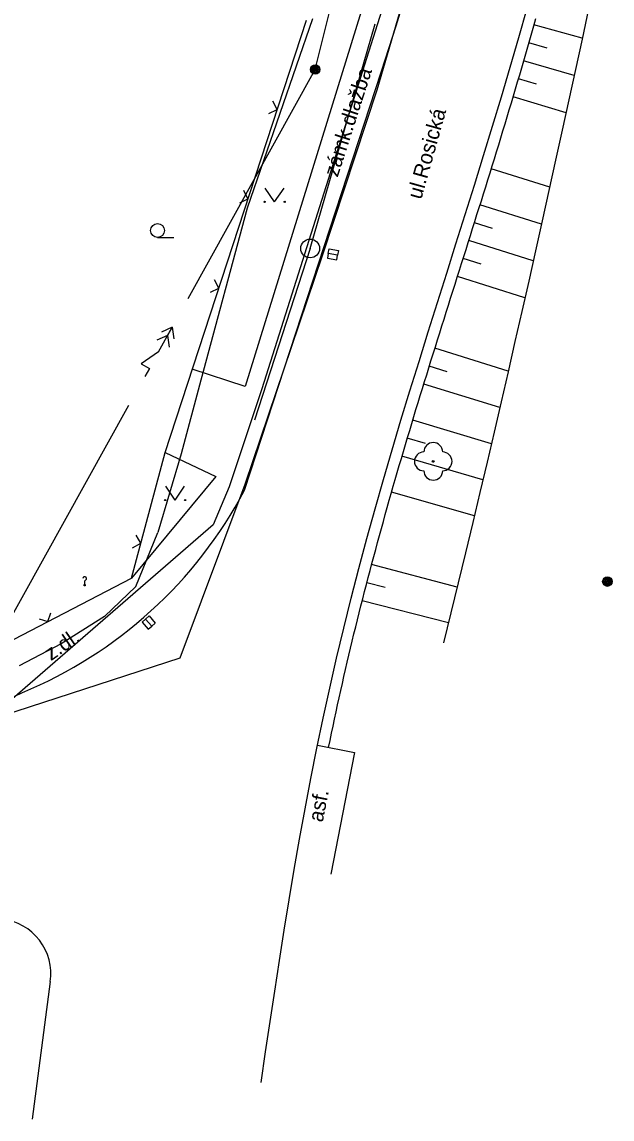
# Model space of a CAD drawing. Extents: x -614582 to -612559, y -1157748 to -1156203.
# Drawn here: x -613339.9 to -613308.5, y -1157413.8 to -1157355.5 of the extents above; entities that cross this region are included whole.
import ezdxf

# ---------------------------------------------------------------- set-up
doc = ezdxf.new("R2010")
doc.units = 0
for name, color, linetype in [('Vrstva 1', 7, 'Continuous'), ('Vrstva 10', 7, 'Continuous'), ('Vrstva 11', 7, 'Continuous'), ('Vrstva 12', 7, 'Continuous'), ('Vrstva 13', 7, 'Continuous'), ('Vrstva 15', 7, 'Continuous'), ('Vrstva 17', 7, 'Continuous'), ('Vrstva 20', 7, 'Continuous'), ('Vrstva 4', 7, 'Continuous'), ('Vrstva 47', 7, 'Continuous'), ('Vrstva 48', 7, 'Continuous'), ('Vrstva 5', 7, 'Continuous'), ('Vrstva 7', 7, 'Continuous'), ('Vrstva 8', 7, 'Continuous')]:
    doc.layers.add(name, color=color, linetype=linetype)

# ---------------------------------------------------------------- blocks, each defined once
blk = doc.blocks.new('SC3403')
at = {"layer": 'Vrstva 10'}
blk.add_lwpolyline([(2.5, 0), (2.5, 2.5), (-2.5, 2.5), (-2.5, 0), (2.5, 0), (2.5, -2.5), (-2.5, -2.5), (-2.5, 0)], dxfattribs=at)
blk = doc.blocks.new('SC3405')
at = {"layer": 'Vrstva 11'}
for radius in [2.5, 2, 1.5, 1, 0.5]:
    blk.add_circle((0, 0), radius, dxfattribs=at)
blk = doc.blocks.new('PLOTDR')
at = {"layer": 'Vrstva 1'}
blk.add_lwpolyline([(-3.5, 3.5), (0, 0), (3.5, 3.5)], dxfattribs=at)
blk = doc.blocks.new('SC3400')
at = {"layer": 'Vrstva 10'}
blk.add_circle((0, 0), 5, dxfattribs=at)
blk = doc.blocks.new('SC3413')
at = {"layer": 'Vrstva 15'}
for points in [[(0, -0.625), (-10, 4.375), (-10, -0.625), (-15, -0.625)], [(10, -0.625), (5, 3.125)], [(15, -0.625), (10, 3.125)], [(0, -0.625), (15, -0.625), (10, -4.375)], [(15, -0.625), (10, -0.625), (5, -4.375)]]:
    blk.add_lwpolyline(points, dxfattribs=at)

msp = doc.modelspace()

# ---------------------------------------------------------------- linework, layer by layer
at = {"layer": 'Vrstva 12'}
for p, q in [((-613310.048, -1157356.334), (-613312.614, -1157355.613)), ((-613311.92, -1157356.851), (-613312.887, -1157356.575)), ((-613310.477, -1157358.314), (-613313.163, -1157357.536)), ((-613312.479, -1157358.779), (-613313.443, -1157358.496)), ((-613310.908, -1157360.294), (-613313.726, -1157359.455)), ((-613311.777, -1157364.246), (-613314.891, -1157363.282)), ((-613312.214, -1157366.216), (-613315.486, -1157365.191)), ((-613314.827, -1157366.447), (-613315.786, -1157366.145)), ((-613312.654, -1157368.182), (-613316.086, -1157367.099)), ((-613315.429, -1157368.355), (-613316.387, -1157368.053)), ((-613313.095, -1157370.141), (-613316.688, -1157369.006)), ((-613313.983, -1157374.041), (-613317.888, -1157372.822)), ((-613317.226, -1157374.074), (-613318.186, -1157373.777)), ((-613314.431, -1157375.979), (-613318.481, -1157374.732)), ((-613314.88, -1157377.909), (-613319.064, -1157376.645)), ((-613318.388, -1157377.891), (-613319.352, -1157377.603)), ((-613315.331, -1157379.829), (-613319.636, -1157378.562)), ((-613315.785, -1157381.741), (-613320.193, -1157380.483)), ((-613316.701, -1157385.545), (-613321.256, -1157384.339)), ((-613320.536, -1157385.558), (-613321.509, -1157385.306)), ((-613317.161, -1157387.439), (-613321.757, -1157386.275))]:
    msp.add_line(p, q, dxfattribs=at)
at = {"layer": 'Vrstva 15'}
for p, q in [((-613324.251, -1157357.996), (-613321.446, -1157346.735)), ((-613331.009, -1157370.179), (-613324.251, -1157357.996)), ((-613340.921, -1157388.046), (-613334.162, -1157375.863))]:
    msp.add_line(p, q, dxfattribs=at)
at = {"layer": 'Vrstva 17'}
for p, q in [((-613320.951, -1157359.076), (-613315.481, -1157340.156)), ((-613323.851, -1157367.846), (-613320.951, -1157359.076)), ((-613327.971, -1157380.056), (-613323.851, -1157367.846)), ((-613331.441, -1157389.296), (-613327.971, -1157380.056)), ((-613340.871, -1157392.376), (-613331.441, -1157389.296))]:
    msp.add_line(p, q, dxfattribs=at)
at = {"layer": 'Vrstva 20'}
for p, q in [((-613317.468, -1157344.596), (-613327.098, -1157374.978)), ((-613317.468, -1157344.596), (-613327.098, -1157374.978)), ((-613327.098, -1157374.978), (-613328.822, -1157380.208)), ((-613327.098, -1157374.978), (-613328.822, -1157380.208)), ((-613328.822, -1157380.208), (-613329.675, -1157382.226)), ((-613328.822, -1157380.208), (-613329.675, -1157382.226)), ((-613329.675, -1157382.226), (-613343.57, -1157394.253)), ((-613329.675, -1157382.226), (-613343.57, -1157394.253))]:
    msp.add_line(p, q, dxfattribs=at)
at = {"layer": 'Vrstva 4'}
for p, q in [((-613318.981, -1157345.736), (-613327.971, -1157374.856)), ((-613328.011, -1157380.386), (-613320.731, -1157358.076)), ((-613327.971, -1157374.856), (-613330.789, -1157373.935)), ((-613332.241, -1157378.376), (-613329.531, -1157379.656)), ((-613329.531, -1157379.656), (-613334.031, -1157385.066)), ((-613324.131, -1157393.956), (-613322.169, -1157394.346)), ((-613322.169, -1157394.346), (-613323.414, -1157400.809)), ((-613338.351, -1157406.526), (-613339.303, -1157413.844))]:
    msp.add_line(p, q, dxfattribs=at)
for points in [[(-613309.711, -1157354.772), (-613310.058, -1157356.383), (-613310.407, -1157357.994), (-613310.758, -1157359.604), (-613311.11, -1157361.214), (-613311.463, -1157362.824), (-613311.819, -1157364.434), (-613312.176, -1157366.043), (-613312.535, -1157367.651), (-613312.896, -1157369.259), (-613313.259, -1157370.867), (-613313.625, -1157372.474), (-613313.992, -1157374.08), (-613314.363, -1157375.686), (-613314.736, -1157377.291), (-613315.111, -1157378.896), (-613315.49, -1157380.5), (-613315.871, -1157382.103), (-613316.256, -1157383.706), (-613316.643, -1157385.308), (-613317.032, -1157386.91), (-613317.423, -1157388.511)], [(-613313.426, -1157356.298), (-613312.983, -1157354.721)], [(-613317.047, -1157370.16), (-613316.93, -1157369.789), (-613316.814, -1157369.419), (-613316.697, -1157369.049), (-613316.58, -1157368.679), (-613316.463, -1157368.308), (-613316.346, -1157367.938), (-613316.229, -1157367.568), (-613316.112, -1157367.197), (-613315.995, -1157366.827), (-613315.878, -1157366.456), (-613315.762, -1157366.086), (-613315.645, -1157365.715), (-613315.529, -1157365.344), (-613315.413, -1157364.973), (-613315.297, -1157364.602), (-613315.181, -1157364.231), (-613315.065, -1157363.86), (-613314.95, -1157363.489), (-613314.835, -1157363.118), (-613314.72, -1157362.746), (-613314.606, -1157362.375), (-613314.492, -1157362.003), (-613314.378, -1157361.632), (-613314.265, -1157361.26), (-613314.152, -1157360.888), (-613314.039, -1157360.515), (-613313.927, -1157360.143), (-613313.815, -1157359.77), (-613313.704, -1157359.398), (-613313.594, -1157359.025), (-613313.483, -1157358.652), (-613313.374, -1157358.278), (-613313.265, -1157357.905), (-613313.156, -1157357.531), (-613313.048, -1157357.158), (-613312.941, -1157356.784), (-613312.834, -1157356.41), (-613312.728, -1157356.035), (-613312.622, -1157355.661), (-613312.517, -1157355.286)], [(-613327.131, -1157411.896), (-613326.89, -1157410.274), (-613326.647, -1157408.653), (-613326.402, -1157407.032), (-613326.152, -1157405.412), (-613325.897, -1157403.793), (-613325.635, -1157402.175), (-613325.363, -1157400.559), (-613325.082, -1157398.945), (-613324.789, -1157397.333), (-613324.484, -1157395.723), (-613324.164, -1157394.116), (-613323.828, -1157392.513), (-613323.477, -1157390.912), (-613323.111, -1157389.315), (-613322.729, -1157387.72), (-613322.334, -1157386.13), (-613321.925, -1157384.542), (-613321.502, -1157382.958), (-613321.066, -1157381.378), (-613320.618, -1157379.802), (-613320.158, -1157378.229), (-613319.69, -1157376.658), (-613319.213, -1157375.09), (-613318.73, -1157373.524), (-613318.242, -1157371.959), (-613317.751, -1157370.395), (-613317.257, -1157368.832), (-613316.764, -1157367.269), (-613316.271, -1157365.706), (-613315.782, -1157364.142), (-613315.296, -1157362.577), (-613314.816, -1157361.011), (-613314.343, -1157359.442), (-613313.879, -1157357.871), (-613313.426, -1157356.298)], [(-613323.542, -1157394.073), (-613323.464, -1157393.694), (-613323.384, -1157393.316), (-613323.304, -1157392.937), (-613323.224, -1157392.559), (-613323.142, -1157392.181), (-613323.059, -1157391.803), (-613322.976, -1157391.425), (-613322.892, -1157391.047), (-613322.806, -1157390.67), (-613322.721, -1157390.292), (-613322.634, -1157389.915), (-613322.546, -1157389.538), (-613322.458, -1157389.161), (-613322.369, -1157388.785), (-613322.278, -1157388.408), (-613322.188, -1157388.032), (-613322.096, -1157387.656), (-613322.003, -1157387.28), (-613321.91, -1157386.905), (-613321.816, -1157386.529), (-613321.721, -1157386.154), (-613321.626, -1157385.779), (-613321.529, -1157385.404), (-613321.432, -1157385.029), (-613321.334, -1157384.654), (-613321.235, -1157384.28), (-613321.135, -1157383.906), (-613321.035, -1157383.532), (-613320.934, -1157383.158), (-613320.832, -1157382.785), (-613320.73, -1157382.411), (-613320.626, -1157382.038), (-613320.522, -1157381.665), (-613320.418, -1157381.292), (-613320.313, -1157380.919), (-613320.207, -1157380.547), (-613320.1, -1157380.174), (-613319.993, -1157379.802), (-613319.885, -1157379.43), (-613319.777, -1157379.058), (-613319.668, -1157378.686), (-613319.558, -1157378.315), (-613319.448, -1157377.943), (-613319.337, -1157377.572), (-613319.226, -1157377.201), (-613319.115, -1157376.829), (-613319.003, -1157376.458), (-613318.89, -1157376.087), (-613318.777, -1157375.716), (-613318.664, -1157375.346), (-613318.55, -1157374.975), (-613318.436, -1157374.604), (-613318.322, -1157374.234), (-613318.207, -1157373.863), (-613318.092, -1157373.493), (-613317.977, -1157373.122), (-613317.861, -1157372.752), (-613317.746, -1157372.381), (-613317.63, -1157372.011), (-613317.513, -1157371.641), (-613317.397, -1157371.271), (-613317.281, -1157370.9), (-613317.164, -1157370.53), (-613317.047, -1157370.16)]]:
    msp.add_lwpolyline(points, dxfattribs=at)
for centre, radius, start, end in [((-613453.386, -1157313.368), 139.987, 341.37473, 357.92912), ((-613348.869, -1157369.349), 23.599, 292.46737, 332.11372), ((-613351.161, -1157368.759), 25.091, 269.04027, 296.79195), ((-613341.214, -1157406.094), 2.896, 351.4174, 83.58582)]:
    msp.add_arc(centre, radius, start, end, dxfattribs=at)
at = {"layer": 'Vrstva 47'}
for p, q in [((-613324.392, -1157355.294), (-613327.876, -1157365.374)), ((-613327.876, -1157365.374), (-613330.328, -1157374.531)), ((-613330.328, -1157374.531), (-613331.387, -1157378.443)), ((-613331.387, -1157378.443), (-613332.615, -1157382.627)), ((-613333.8, -1157385.507), (-613332.615, -1157382.627)), ((-613333.8, -1157385.507), (-613335.461, -1157387.107)), ((-613335.461, -1157387.107), (-613337.764, -1157388.549)), ((-613337.764, -1157388.549), (-613339.992, -1157389.726))]:
    msp.add_line(p, q, dxfattribs=at)
at = {"layer": 'Vrstva 48'}
for q in [(-613321.055, -1157355.558), (-613327.477, -1157376.662)]:
    msp.add_line((-613324.521, -1157367.516), q, dxfattribs=at)
at = {"layer": 'Vrstva 5'}
for p, q in [((-613332.241, -1157378.376), (-613324.721, -1157355.366)), ((-613334.031, -1157385.066), (-613332.241, -1157378.376)), ((-613345.681, -1157391.126), (-613334.031, -1157385.066))]:
    msp.add_line(p, q, dxfattribs=at)
at = {"layer": 'Vrstva 7'}
for points in [[(-613326.409, -1157365.034), (-613326.909, -1157364.3)], [(-613326.409, -1157365.034), (-613325.909, -1157364.3)], [(-613332.638, -1157366.924), (-613332.138, -1157366.924), (-613331.771, -1157366.924)], [(-613331.702, -1157380.903), (-613332.202, -1157380.17)], [(-613331.702, -1157380.903), (-613331.202, -1157380.17)]]:
    msp.add_lwpolyline(points, dxfattribs=at)
for centre, radius in [((-613326.942, -1157365.034), 0.0333), ((-613325.875, -1157365.034), 0.0333), ((-613332.638, -1157366.558), 0.367), ((-613317.971, -1157378.846), 0.05), ((-613332.235, -1157380.903), 0.0333), ((-613331.169, -1157380.903), 0.0333)]:
    msp.add_circle(centre, radius, dxfattribs=at)
for centre, start, end in [((-613317.971, -1157378.346), 0, 180), ((-613318.471, -1157378.846), 90, 270), ((-613317.471, -1157378.846), 270, 90), ((-613317.971, -1157379.346), 180, 0)]:
    msp.add_arc(centre, 0.5, start, end, dxfattribs=at)
at = {"layer": 'Vrstva 8'}
for points in [[(-613336.601, -1157385.055), (-613336.56, -1157384.976), (-613336.474, -1157384.976), (-613336.431, -1157385.055), (-613336.431, -1157385.138), (-613336.517, -1157385.22), (-613336.517, -1157385.354)], [(-613336.537, -1157385.398), (-613336.494, -1157385.398), (-613336.494, -1157385.476), (-613336.537, -1157385.476), (-613336.537, -1157385.398)]]:
    msp.add_lwpolyline(points, dxfattribs=at)

# ---------------------------------------------------------------- block references
at = {"layer": 'Vrstva 10', "xscale": 0.1}
for p, yscale, rotation in [((-613323.311, -1157367.826), 0.09999999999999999, 169.79303211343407), ((-613333.111, -1157387.426), 0.09999999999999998, 130.18684044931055)]:
    msp.add_blockref('SC3403', p, dxfattribs=dict(at, yscale=yscale, rotation=rotation))
at = {"layer": 'Vrstva 11', "xscale": 0.1, "yscale": 0.10000000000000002}
for p in [(-613324.251, -1157357.996), (-613308.711, -1157385.246)]:
    msp.add_blockref('SC3405', p, dxfattribs=at)
at = {"layer": 'Vrstva 15', "xscale": 0.09999999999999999, "yscale": 0.1, "rotation": 60.981023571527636}
msp.add_blockref('SC3413', (-613332.641, -1157372.991), dxfattribs=at)
at = {"layer": 'Vrstva 48', "xscale": 0.1, "yscale": 0.10000000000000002}
msp.add_blockref('SC3400', (-613324.521, -1157367.516), dxfattribs=at)
at = {"layer": 'Vrstva 5'}
for p, xscale, yscale, rotation in [((-613326.274, -1157360.119), 0.09999999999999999, 0.1, 71.90186115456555), ((-613327.827, -1157364.872), 0.09999999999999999, 0.1, 71.90186115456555), ((-613329.381, -1157369.624), 0.09999999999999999, 0.1, 71.90186115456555), ((-613333.533, -1157383.206), 0.1, 0.09999999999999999, 75.02061873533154), ((-613338.467, -1157387.374), 0.09999999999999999, 0.10000000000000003, 27.482173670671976)]:
    msp.add_blockref('PLOTDR', p, dxfattribs=dict(at, xscale=xscale, yscale=yscale, rotation=rotation))

# ---------------------------------------------------------------- texts
at = {"layer": 'Vrstva 13'}
for s, rotation, p in [('zámk.dlažba', 72.16898, (-613323.06, -1157363.762)), ('ul.Rosická', 74.32708, (-613318.612, -1157364.942)), ('z.dl.', 34.70516, (-613338.307, -1157389.484)), ('asf.', 78.95124, (-613323.852, -1157398.079))]:
    msp.add_text(s, height=0.8, rotation=rotation, dxfattribs=at).set_placement(p)

doc.saveas('drawing.dxf')
